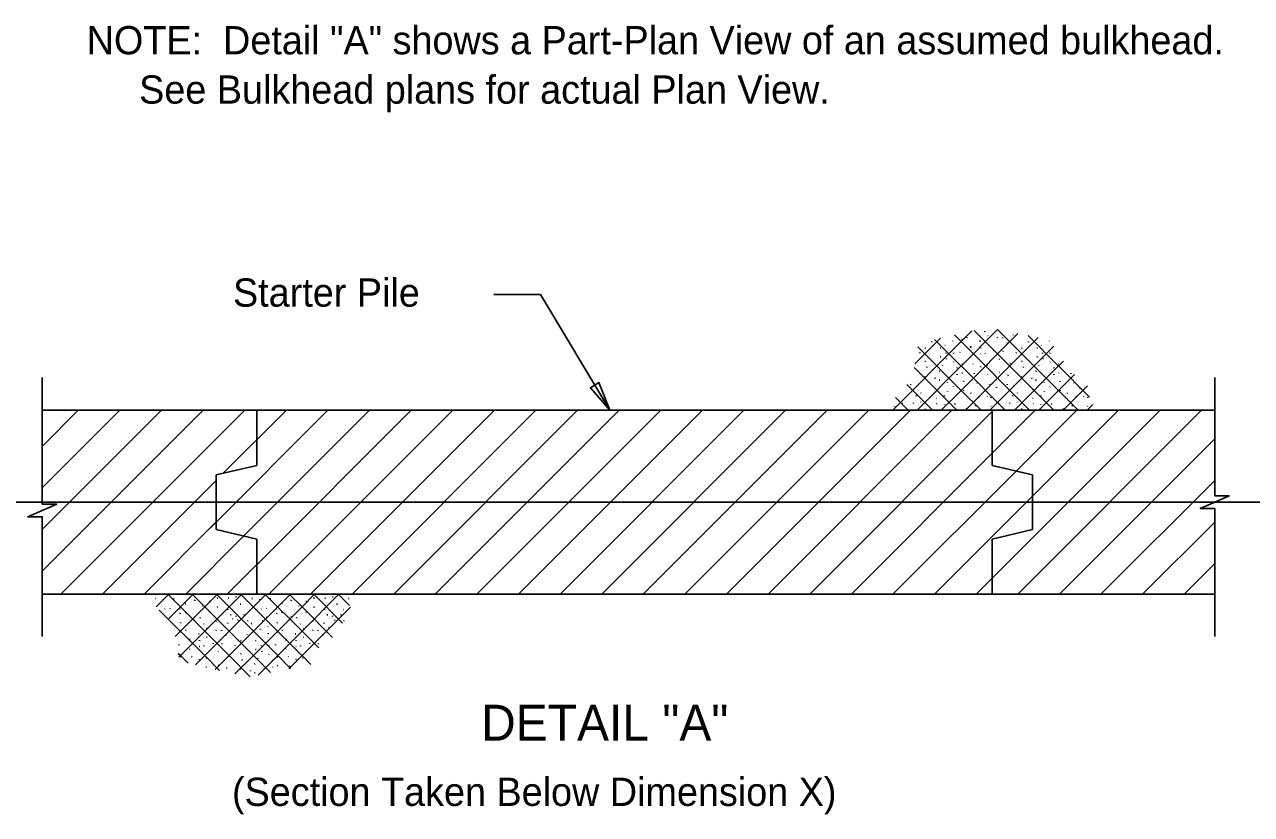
# Model space of a CAD drawing. Extents: x 0.4 to 30.4, y 0.1 to 19.4.
# Drawn here: x 4.37 to 10.94, y 0.94 to 5.17 of the extents above; entities that cross this region are included whole.
import ezdxf

# ---------------------------------------------------------------- set-up
doc = ezdxf.new("R2010")
doc.units = 0
for name, color, linetype in [('Dimension', 7, 'Continuous'), ('Miscellaneous', 7, 'Continuous'), ('SheetPileConc', 7, 'Continuous'), ('TextStructures', 7, 'Continuous')]:
    doc.layers.add(name, color=color, linetype=linetype)

msp = doc.modelspace()

# ---------------------------------------------------------------- linework, layer by layer
at = {"layer": 'Dimension'}
for p, q in [((7.1326, 3.7252), (6.8827, 3.7252)), ((7.1326, 3.7252), (7.5037, 3.1066)), ((4.4653, 2.6773), (4.4653, 3.2816)), ((10.7426, 2.7215), (10.7426, 3.2816)), ((10.7426, 1.8953), (10.7426, 2.5109)), ((4.4653, 1.8953), (4.4653, 2.4666))]:
    msp.add_line(p, q, dxfattribs=at)
msp.add_lwpolyline([(7.5037, 3.1066), (7.4461, 3.2542), (7.4007, 3.2269)], close=True, dxfattribs=at)
for points in [[(10.7426, 2.7213), (10.7426, 2.6488), (10.8201, 2.6488), (10.7426, 2.615), (10.6651, 2.5813), (10.7426, 2.5813), (10.7426, 2.5088)], [(4.4653, 2.677), (4.4653, 2.6045), (4.5428, 2.6045), (4.4653, 2.5708), (4.3878, 2.537), (4.4653, 2.537), (4.4653, 2.4645)]]:
    msp.add_lwpolyline(points, dxfattribs=at)
at = {"layer": 'Miscellaneous'}
for p, q in [((9.1373, 3.3555), (9.2742, 3.4924)), ((9.3854, 3.3431), (9.2432, 3.4853)), ((9.3854, 3.4734), (9.3492, 3.5096)), ((9.3854, 3.3431), (9.5807, 3.5385)), ((9.3854, 3.4734), (9.4431, 3.5311)), ((9.3854, 3.2129), (9.6891, 3.5167)), ((9.3888, 3.4853), (9.3904, 3.4891)), ((9.409, 3.1063), (9.7974, 3.4948)), ((9.4159, 3.4937), (9.4166, 3.4966)), ((9.8835, 3.1055), (9.4551, 3.5338)), ((9.5121, 3.5267), (9.5129, 3.5298)), ((9.5302, 3.5049), (9.5279, 3.5057)), ((9.5775, 3.4944), (9.579, 3.4974)), ((9.9062, 3.2129), (9.5806, 3.5385)), ((9.607, 3.4927), (9.6078, 3.4958)), ((9.6658, 3.5079), (9.6651, 3.5094)), ((9.9062, 3.3431), (9.7438, 3.5056)), ((9.0191, 3.1071), (9.3854, 3.4734)), ((9.3854, 3.2129), (9.1535, 3.4448)), ((9.1933, 3.4365), (9.194, 3.4395)), ((9.229, 3.4714), (9.2297, 3.4743)), ((9.2768, 3.4395), (9.273, 3.4387)), ((9.2993, 3.4523), (9.2971, 3.4546)), ((9.34, 3.4756), (9.3407, 3.4786)), ((9.379, 3.4151), (9.3797, 3.418)), ((9.753, 3.1057), (9.3854, 3.4734)), ((9.4346, 3.4402), (9.4362, 3.4433)), ((9.4362, 3.4455), (9.4369, 3.4486)), ((9.4881, 3.4763), (9.4842, 3.4756)), ((9.4891, 3.4385), (9.4899, 3.4415)), ((9.5302, 3.4575), (9.5279, 3.4583)), ((9.539, 3.1061), (9.8813, 3.4485)), ((9.5625, 3.423), (9.5633, 3.426)), ((9.6087, 3.4208), (9.6102, 3.4238)), ((9.6308, 3.4645), (9.6315, 3.4674)), ((9.7102, 3.4365), (9.7109, 3.4395)), ((9.7459, 3.4714), (9.7466, 3.4743)), ((9.7936, 3.4395), (9.7899, 3.4387)), ((9.8162, 3.4523), (9.814, 3.4546)), ((9.8569, 3.4756), (9.8576, 3.4786)), ((9.1632, 3.4124), (9.1639, 3.4154)), ((9.1933, 3.3673), (9.194, 3.3703)), ((9.2768, 3.3922), (9.273, 3.3914)), ((9.3038, 3.4102), (9.3046, 3.4132)), ((9.3063, 3.3799), (9.3071, 3.3829)), ((9.3437, 3.4102), (9.3444, 3.4132)), ((9.3437, 3.3628), (9.3444, 3.3658)), ((9.3918, 3.3531), (9.3888, 3.3523)), ((9.4346, 3.3929), (9.4362, 3.3959)), ((9.4497, 3.3531), (9.4475, 3.3553)), ((9.4911, 3.4079), (9.4881, 3.4072)), ((9.5136, 3.4094), (9.5143, 3.4124)), ((9.5893, 3.3786), (9.5907, 3.3816)), ((9.65, 3.3553), (9.6485, 3.3575)), ((9.6801, 3.4124), (9.6808, 3.4154)), ((9.7102, 3.3673), (9.7109, 3.3703)), ((9.7936, 3.3922), (9.7899, 3.3914)), ((9.8207, 3.4102), (9.8214, 3.4132)), ((9.8232, 3.3799), (9.824, 3.3829)), ((9.8606, 3.4102), (9.8613, 3.4132)), ((9.8606, 3.3628), (9.8613, 3.3658)), ((9.9087, 3.3531), (9.9057, 3.3523)), ((9.9062, 3.3431), (9.9328, 3.3697)), ((9.3617, 3.1064), (9.1335, 3.3346)), ((9.1491, 3.1068), (9.3854, 3.3432)), ((9.1903, 3.2846), (9.191, 3.2876)), ((9.2008, 3.3353), (9.2016, 3.3383)), ((9.2715, 3.3146), (9.267, 3.3139)), ((9.285, 3.3433), (9.2858, 3.3462)), ((9.3639, 3.332), (9.3647, 3.335)), ((9.3639, 3.2966), (9.3647, 3.2996)), ((9.6226, 3.1059), (9.3854, 3.3432)), ((9.3918, 3.3057), (9.3888, 3.3049)), ((9.4549, 3.3012), (9.4557, 3.3042)), ((9.4888, 3.3372), (9.4904, 3.3402)), ((9.5271, 3.347), (9.5242, 3.3455)), ((9.5271, 3.2996), (9.5242, 3.2982)), ((9.5908, 3.3079), (9.5894, 3.3102)), ((9.638, 3.2937), (9.6342, 3.2929)), ((9.6689, 3.1059), (9.9062, 3.3432)), ((9.7072, 3.2846), (9.7079, 3.2876)), ((9.7177, 3.3353), (9.7185, 3.3383)), ((9.7884, 3.3146), (9.7839, 3.3139)), ((9.8019, 3.3433), (9.8027, 3.3462)), ((9.8808, 3.332), (9.8816, 3.335)), ((9.8808, 3.2966), (9.8816, 3.2996)), ((9.9087, 3.3057), (9.9057, 3.3049)), ((10.0725, 3.1768), (9.9062, 3.3432)), ((9.9062, 3.2129), (9.9916, 3.2983)), ((9.9718, 3.3012), (9.9726, 3.3042)), ((9.2312, 3.1067), (9.0943, 3.2436)), ((9.1143, 3.2427), (9.115, 3.2457)), ((9.1505, 3.235), (9.1512, 3.238)), ((9.246, 3.2763), (9.2467, 3.2794)), ((9.2512, 3.2161), (9.2527, 3.2192)), ((9.2715, 3.2673), (9.267, 3.2665)), ((9.3128, 3.2545), (9.3121, 3.256)), ((9.3437, 3.2312), (9.3444, 3.2342)), ((9.3986, 3.2583), (9.3993, 3.262)), ((9.4708, 3.2516), (9.4693, 3.2523)), ((9.5053, 3.2244), (9.5023, 3.223)), ((9.5369, 3.2432), (9.5362, 3.2447)), ((9.5738, 3.2267), (9.5745, 3.2297)), ((9.6311, 3.2427), (9.6319, 3.2457)), ((9.6673, 3.235), (9.6681, 3.238)), ((9.7629, 3.2763), (9.7636, 3.2794)), ((9.7681, 3.2161), (9.7696, 3.2192)), ((9.7884, 3.2673), (9.7839, 3.2665)), ((9.8297, 3.2545), (9.829, 3.256)), ((9.8606, 3.2312), (9.8613, 3.2342)), ((9.9155, 3.2583), (9.9162, 3.262)), ((9.9289, 3.1054), (10.061, 3.2375)), ((9.9877, 3.2516), (9.9862, 3.2523)), ((10.0222, 3.2244), (10.0192, 3.223)), ((9.1008, 3.1069), (9.0329, 3.1748)), ((9.1436, 3.1824), (9.1444, 3.1853)), ((9.1693, 3.1974), (9.17, 3.2004)), ((9.2512, 3.1688), (9.2527, 3.1718)), ((9.279, 3.1066), (9.3854, 3.2129)), ((9.2956, 3.1824), (9.2956, 3.1853)), ((9.3128, 3.2072), (9.3121, 3.2087)), ((9.4921, 3.1062), (9.3854, 3.2129)), ((9.3986, 3.2109), (9.3993, 3.2146)), ((9.4362, 3.1958), (9.4369, 3.1989)), ((9.4835, 3.1786), (9.4798, 3.1779)), ((9.5256, 3.1801), (9.5242, 3.1824)), ((9.5444, 3.1733), (9.546, 3.1763)), ((9.6605, 3.1824), (9.6613, 3.1853)), ((9.6862, 3.1974), (9.6869, 3.2004)), ((9.7681, 3.1688), (9.7696, 3.1718)), ((9.7989, 3.1056), (9.9062, 3.2129)), ((9.8125, 3.1824), (9.8125, 3.1853)), ((9.8297, 3.2072), (9.829, 3.2087)), ((10.0139, 3.1052), (9.9062, 3.2129)), ((9.9155, 3.2109), (9.9162, 3.2146)), ((9.9531, 3.1958), (9.9538, 3.1989)), ((10.0004, 3.1786), (9.9967, 3.1779)), ((10.0425, 3.1801), (10.041, 3.1824)), ((10.0613, 3.1733), (10.0629, 3.1763)), ((4.4653, 2.9132), (4.6587, 3.1066)), ((4.4653, 2.6905), (4.8814, 3.1066)), ((4.4653, 2.4678), (5.1042, 3.1066)), ((4.4653, 2.245), (5.3269, 3.1066)), ((4.5653, 2.1223), (5.5497, 3.1066)), ((5.3648, 2.4764), (5.9951, 3.1066)), ((5.4348, 2.7691), (5.7724, 3.1066)), ((5.545, 2.4338), (6.2178, 3.1066)), ((5.6137, 2.2797), (6.4406, 3.1066)), ((5.679, 2.1223), (6.6633, 3.1066)), ((5.9017, 2.1223), (6.8861, 3.1066)), ((6.1244, 2.1223), (7.1088, 3.1066)), ((6.3472, 2.1223), (7.3315, 3.1066)), ((6.5699, 2.1223), (7.5543, 3.1066)), ((6.7926, 2.1223), (7.777, 3.1066)), ((7.0154, 2.1223), (7.9998, 3.1066)), ((7.2381, 2.1223), (8.2225, 3.1066)), ((7.4608, 2.1223), (8.4452, 3.1066)), ((7.6836, 2.1223), (8.6679, 3.1066)), ((7.9063, 2.1223), (8.8907, 3.1066)), ((8.1291, 2.1223), (9.1134, 3.1066)), ((8.3518, 2.1223), (9.3362, 3.1066)), ((8.5745, 2.1223), (9.5589, 3.1066)), ((9.0275, 3.1259), (9.0291, 3.129)), ((9.071, 3.144), (9.0672, 3.1432)), ((9.1301, 3.144), (9.1264, 3.1432)), ((9.1693, 3.1492), (9.17, 3.1523)), ((9.1948, 3.1117), (9.1903, 3.1117)), ((9.2564, 3.1417), (9.2534, 3.141)), ((9.2956, 3.135), (9.2956, 3.138)), ((9.3542, 3.1402), (9.3505, 3.1395)), ((9.4136, 3.1124), (9.4159, 3.1154)), ((9.4625, 3.1305), (9.464, 3.1335)), ((9.464, 3.129), (9.4647, 3.132)), ((9.4655, 2.1223), (10.4499, 3.1066)), ((9.4663, 2.7912), (9.7816, 3.1066)), ((9.534, 2.4135), (10.2271, 3.1066)), ((9.5444, 3.1259), (9.546, 3.129)), ((9.5879, 3.144), (9.5841, 3.1432)), ((9.647, 3.144), (9.6433, 3.1432)), ((9.6789, 2.7811), (10.0044, 3.1066)), ((9.6862, 3.1492), (9.6869, 3.1523)), ((9.6882, 2.1223), (10.6726, 3.1066)), ((9.7117, 3.1117), (9.7072, 3.1117)), ((9.7733, 3.1417), (9.7703, 3.141)), ((9.8125, 3.135), (9.8125, 3.138)), ((9.8711, 3.1402), (9.8673, 3.1395)), ((9.9305, 3.1124), (9.9328, 3.1154)), ((9.9794, 3.1305), (9.9809, 3.1335)), ((9.9809, 3.129), (9.9816, 3.132)), ((10.0588, 3.1051), (10.0902, 3.1365)), ((10.0613, 3.1259), (10.0629, 3.129)), ((9.911, 2.1223), (10.7426, 2.9539)), ((8.7973, 2.1223), (9.5512, 2.8761)), ((9.02, 2.1223), (9.679, 2.7811)), ((4.788, 2.1223), (5.3972, 2.7314)), ((10.1337, 2.1223), (10.7426, 2.7312)), ((4.4653, 2.6144), (4.0715, 2.6144)), ((10.7426, 2.6144), (4.4653, 2.6144)), ((10.7426, 2.6144), (11.1364, 2.6144)), ((5.0107, 2.1223), (5.3972, 2.5086)), ((10.3564, 2.1223), (10.7426, 2.5084)), ((5.2335, 2.1223), (5.545, 2.4338)), ((5.4562, 2.1223), (5.7942, 2.4603)), ((9.2427, 2.1223), (9.5405, 2.4201)), ((10.5791, 2.1223), (10.7426, 2.2858)), ((5.0761, 2.0555), (5.1426, 2.122)), ((5.1375, 1.9866), (5.2731, 2.1222)), ((5.3355, 1.9242), (5.1378, 2.122)), ((5.3355, 2.0544), (5.2678, 2.1222)), ((5.3355, 1.794), (5.6644, 2.1229)), ((5.3355, 1.9242), (5.534, 2.1227)), ((5.3355, 2.0544), (5.4035, 2.1225)), ((5.7262, 1.794), (5.3978, 2.1224)), ((5.4657, 1.794), (5.7948, 2.1232)), ((5.5039, 2.1071), (5.5046, 2.1102)), ((5.8561, 1.7943), (5.5277, 2.1227)), ((5.8564, 1.9242), (5.6577, 2.1229)), ((5.8564, 2.0544), (5.7877, 2.1232)), ((5.8564, 1.9242), (6.0558, 2.1237)), ((5.8564, 2.0544), (5.9253, 2.1234)), ((6.0737, 1.9674), (5.9177, 2.1234)), ((6.0208, 2.1071), (6.0215, 2.1102)), ((6.1101, 2.0612), (6.0476, 2.1236)), ((6.1786, 2.1229), (6.1776, 2.1239)), ((5.0742, 2.0996), (5.0712, 2.0989)), ((5.3353, 1.7943), (5.0922, 2.0373)), ((5.1133, 2.0928), (5.1133, 2.0958)), ((5.1215, 2.0417), (5.1223, 2.0447)), ((5.1509, 2.0462), (5.1501, 2.0477)), ((5.1719, 2.0981), (5.1682, 2.0973)), ((5.1776, 1.8965), (5.3355, 2.0545)), ((5.2035, 2.0417), (5.2042, 2.0447)), ((5.2313, 2.0703), (5.2336, 2.0732)), ((5.2802, 2.0883), (5.2817, 2.0913)), ((5.2817, 2.0868), (5.2824, 2.0898)), ((5.3231, 2.0583), (5.3216, 2.0605)), ((5.596, 1.794), (5.3355, 2.0545)), ((5.3621, 2.0838), (5.3637, 2.0868)), ((5.4056, 2.1019), (5.4018, 2.1011)), ((5.4056, 2.0545), (5.4018, 2.0537)), ((5.4591, 2.0387), (5.4599, 2.0417)), ((5.4648, 2.1019), (5.461, 2.1011)), ((5.5294, 2.0695), (5.5249, 2.0695)), ((5.5633, 2.0402), (5.5618, 2.0409)), ((5.5911, 2.0996), (5.5881, 2.0989)), ((5.596, 1.794), (5.8564, 2.0545)), ((5.6302, 2.0928), (5.6302, 2.0958)), ((5.6384, 2.0417), (5.6392, 2.0447)), ((5.6677, 2.0462), (5.667, 2.0477)), ((5.6888, 2.0981), (5.6851, 2.0973)), ((5.7204, 2.0417), (5.7211, 2.0447)), ((5.7482, 2.0703), (5.7505, 2.0732)), ((5.7971, 2.0883), (5.7986, 2.0913)), ((5.7986, 2.0868), (5.7993, 2.0898)), ((5.8399, 2.0583), (5.8385, 2.0605)), ((6.0196, 1.8912), (5.8564, 2.0545)), ((5.8564, 1.794), (6.1159, 2.0535)), ((5.879, 2.0838), (5.8806, 2.0868)), ((5.9225, 2.1019), (5.9187, 2.1011)), ((5.9225, 2.0545), (5.9187, 2.0537)), ((5.976, 2.0387), (5.9768, 2.0417)), ((5.9816, 2.1019), (5.9779, 2.1011)), ((6.0463, 2.0695), (6.0418, 2.0695)), ((6.0802, 2.0402), (6.0787, 2.0409)), ((6.108, 2.0996), (6.105, 2.0989)), ((5.1509, 1.9989), (5.1501, 2.0004)), ((5.2035, 2.0176), (5.2042, 2.0206)), ((5.2065, 1.9673), (5.2081, 1.971)), ((5.2313, 2.0229), (5.2336, 2.0259)), ((5.278, 1.9838), (5.2794, 1.9869)), ((5.2817, 1.9996), (5.2824, 2.0026)), ((5.3103, 1.9935), (5.3118, 1.9973)), ((5.3614, 2.0259), (5.3607, 2.0274)), ((5.3645, 2.0282), (5.3614, 2.0282)), ((5.3953, 1.9763), (5.3968, 1.9793)), ((5.4768, 2.0124), (5.473, 2.0116)), ((5.4836, 1.9898), (5.4831, 1.9906)), ((5.5023, 2.0033), (5.5031, 2.0064)), ((5.5136, 1.9815), (5.5151, 1.9853)), ((5.5467, 2.0102), (5.5474, 2.0131)), ((5.564, 1.9785), (5.5655, 1.9815)), ((5.6474, 1.9815), (5.6437, 1.98)), ((5.6677, 1.9989), (5.667, 2.0004)), ((5.7204, 2.0176), (5.7211, 2.0206)), ((5.7234, 1.9673), (5.725, 1.971)), ((5.7482, 2.0229), (5.7505, 2.0259)), ((5.7949, 1.9838), (5.7963, 1.9869)), ((5.7986, 1.9996), (5.7993, 2.0026)), ((5.8272, 1.9935), (5.8287, 1.9973)), ((5.8783, 2.0259), (5.8776, 2.0274)), ((5.8814, 2.0282), (5.8783, 2.0282)), ((5.9122, 1.9763), (5.9136, 1.9793)), ((5.9937, 2.0124), (5.9899, 2.0116)), ((6.0005, 1.9898), (6, 1.9906)), ((6.0192, 2.0033), (6.02, 2.0064)), ((6.0305, 1.9815), (6.032, 1.9853)), ((6.0636, 2.0102), (6.0643, 2.0131)), ((6.0809, 1.9785), (6.0824, 1.9815)), ((5.2053, 1.794), (5.3355, 1.9242)), ((5.2065, 1.9199), (5.2081, 1.9237)), ((5.2336, 1.9282), (5.2343, 1.9311)), ((5.3058, 1.9108), (5.302, 1.9101)), ((5.3298, 1.9612), (5.3306, 1.9643)), ((5.4657, 1.794), (5.3355, 1.9242)), ((5.3479, 1.9395), (5.3456, 1.9402)), ((5.3953, 1.9289), (5.3968, 1.9319)), ((5.4247, 1.9272), (5.4255, 1.9303)), ((5.4576, 1.9658), (5.4583, 1.9688)), ((5.4836, 1.9425), (5.4828, 1.944)), ((5.5636, 1.9059), (5.5644, 1.9089)), ((5.5881, 1.9658), (5.5844, 1.965)), ((5.634, 1.9342), (5.6317, 1.9365)), ((5.6738, 1.947), (5.6746, 1.95)), ((5.6746, 1.9101), (5.6753, 1.9132)), ((5.7234, 1.9199), (5.725, 1.9237)), ((5.7262, 1.794), (5.8564, 1.9242)), ((5.7505, 1.9282), (5.7512, 1.9311)), ((5.8227, 1.9108), (5.8189, 1.9101)), ((5.8467, 1.9612), (5.8475, 1.9643)), ((5.9455, 1.8351), (5.8564, 1.9242)), ((5.8648, 1.9395), (5.8625, 1.9402)), ((5.9122, 1.9289), (5.9136, 1.9319)), ((5.9416, 1.9272), (5.9424, 1.9303)), ((5.9745, 1.9658), (5.9752, 1.9688)), ((6.0005, 1.9425), (5.9997, 1.944)), ((5.1967, 1.8496), (5.1975, 1.8526)), ((5.2524, 1.8748), (5.2539, 1.8778)), ((5.2539, 1.88), (5.2546, 1.8831)), ((5.3088, 1.8425), (5.3058, 1.8417)), ((5.3068, 1.8731), (5.3076, 1.876)), ((5.3313, 1.844), (5.332, 1.847)), ((5.3479, 1.8921), (5.3456, 1.8929)), ((5.3802, 1.8575), (5.381, 1.8605)), ((5.4264, 1.8554), (5.4279, 1.8584)), ((5.4485, 1.899), (5.4493, 1.902)), ((5.4978, 1.847), (5.4985, 1.85)), ((5.5279, 1.871), (5.5286, 1.874)), ((5.6114, 1.874), (5.6076, 1.8733)), ((5.634, 1.8869), (5.6317, 1.8891)), ((5.6384, 1.8447), (5.6392, 1.8477)), ((5.6783, 1.8447), (5.679, 1.8477)), ((5.7136, 1.8496), (5.7144, 1.8526)), ((5.7692, 1.8748), (5.7708, 1.8778)), ((5.7708, 1.88), (5.7715, 1.8831)), ((5.8257, 1.8425), (5.8227, 1.8417)), ((5.8237, 1.8731), (5.8245, 1.876)), ((5.8482, 1.844), (5.8489, 1.847)), ((5.8648, 1.8921), (5.8625, 1.8929)), ((5.8971, 1.8575), (5.8979, 1.8605)), ((5.9433, 1.8554), (5.9448, 1.8584)), ((5.9654, 1.899), (5.9662, 1.902)), ((5.2053, 1.794), (5.1941, 1.8052)), ((5.1975, 1.7862), (5.2053, 1.794)), ((5.2463, 1.7531), (5.2053, 1.794)), ((5.2095, 1.7876), (5.2065, 1.7868)), ((5.2524, 1.8274), (5.2539, 1.8304)), ((5.2675, 1.7876), (5.2652, 1.7898)), ((5.2856, 1.7441), (5.3355, 1.794)), ((5.3065, 1.7718), (5.3081, 1.7748)), ((5.4152, 1.7144), (5.3355, 1.794)), ((5.3449, 1.7815), (5.3419, 1.78)), ((5.3915, 1.7198), (5.4657, 1.794)), ((5.407, 1.8132), (5.4084, 1.8162)), ((5.5788, 1.681), (5.4657, 1.794)), ((5.4677, 1.7898), (5.4663, 1.7921)), ((5.4975, 1.6955), (5.596, 1.794)), ((5.5279, 1.8018), (5.5286, 1.8048)), ((5.6871, 1.7029), (5.596, 1.794)), ((5.6114, 1.8267), (5.6076, 1.8259)), ((5.6196, 1.7778), (5.6204, 1.7808)), ((5.6218, 1.6897), (5.7262, 1.794)), ((5.6409, 1.8145), (5.6417, 1.8174)), ((5.6783, 1.7974), (5.679, 1.8003)), ((5.7264, 1.7876), (5.7234, 1.7868)), ((5.7955, 1.7247), (5.7262, 1.794)), ((5.7692, 1.8274), (5.7708, 1.8304)), ((5.7844, 1.7876), (5.7821, 1.7898)), ((5.785, 1.7226), (5.8564, 1.794)), ((5.8234, 1.7718), (5.825, 1.7748)), ((5.9038, 1.7466), (5.8564, 1.794)), ((5.8618, 1.7815), (5.8588, 1.78)), ((5.3449, 1.7341), (5.3419, 1.7327)), ((5.4086, 1.7425), (5.4071, 1.7447)), ((5.4557, 1.7282), (5.4519, 1.7274)), ((5.5249, 1.7191), (5.5256, 1.7222)), ((5.5355, 1.7699), (5.5362, 1.7728)), ((5.5806, 1.7108), (5.5813, 1.7139)), ((5.6061, 1.7492), (5.6016, 1.7485)), ((5.6985, 1.7666), (5.6993, 1.7695)), ((5.6985, 1.7311), (5.6993, 1.7341)), ((5.7264, 1.7402), (5.7234, 1.7394)), ((5.7896, 1.7357), (5.7903, 1.7387)), ((5.6061, 1.7018), (5.6016, 1.7011))]:
    msp.add_line(p, q, dxfattribs=at)
at = {"layer": 'SheetPileConc'}
for p, q in [((4.4653, 3.1066), (9.5512, 3.1066)), ((5.6137, 3.1066), (5.6137, 2.8113)), ((9.5512, 3.1066), (9.5512, 2.8113)), ((9.5512, 3.1066), (10.7426, 3.1066)), ((5.6137, 2.8113), (5.3972, 2.7601)), ((5.3972, 2.7601), (5.3972, 2.4687)), ((9.7677, 2.7601), (9.5512, 2.8113)), ((9.7677, 2.4687), (9.7677, 2.7601)), ((5.3972, 2.4687), (5.6137, 2.4176)), ((9.5512, 2.4176), (9.7677, 2.4687)), ((5.6137, 2.1223), (5.6137, 2.4176)), ((9.5512, 2.1223), (9.5512, 2.4176)), ((9.5512, 2.1223), (4.4653, 2.1223)), ((10.7426, 2.1223), (9.5512, 2.1223))]:
    msp.add_line(p, q, dxfattribs=at)

# ---------------------------------------------------------------- texts
at = {"layer": 'Dimension'}
for s, p in [('NOTE:  Detail "A" shows a Part-Plan View of an assumed bulkhead. ', (4.7034, 5.0105)), ('     See Bulkhead plans for actual Plan View.            ', (4.7034, 4.7465))]:
    msp.add_text(s, height=0.1512, dxfattribs=at).set_placement(p)
at = {"layer": 'TextStructures'}
for s, height, p in [('Starter Pile', 0.1512, (5.487, 3.6605)), ('DETAIL "A"', 0.192, (6.8152, 1.3388)), ('(Section Taken Below Dimension X)', 0.1512, (5.4814, 0.9896))]:
    msp.add_text(s, height=height, dxfattribs=at).set_placement(p)

doc.saveas('drawing.dxf')
